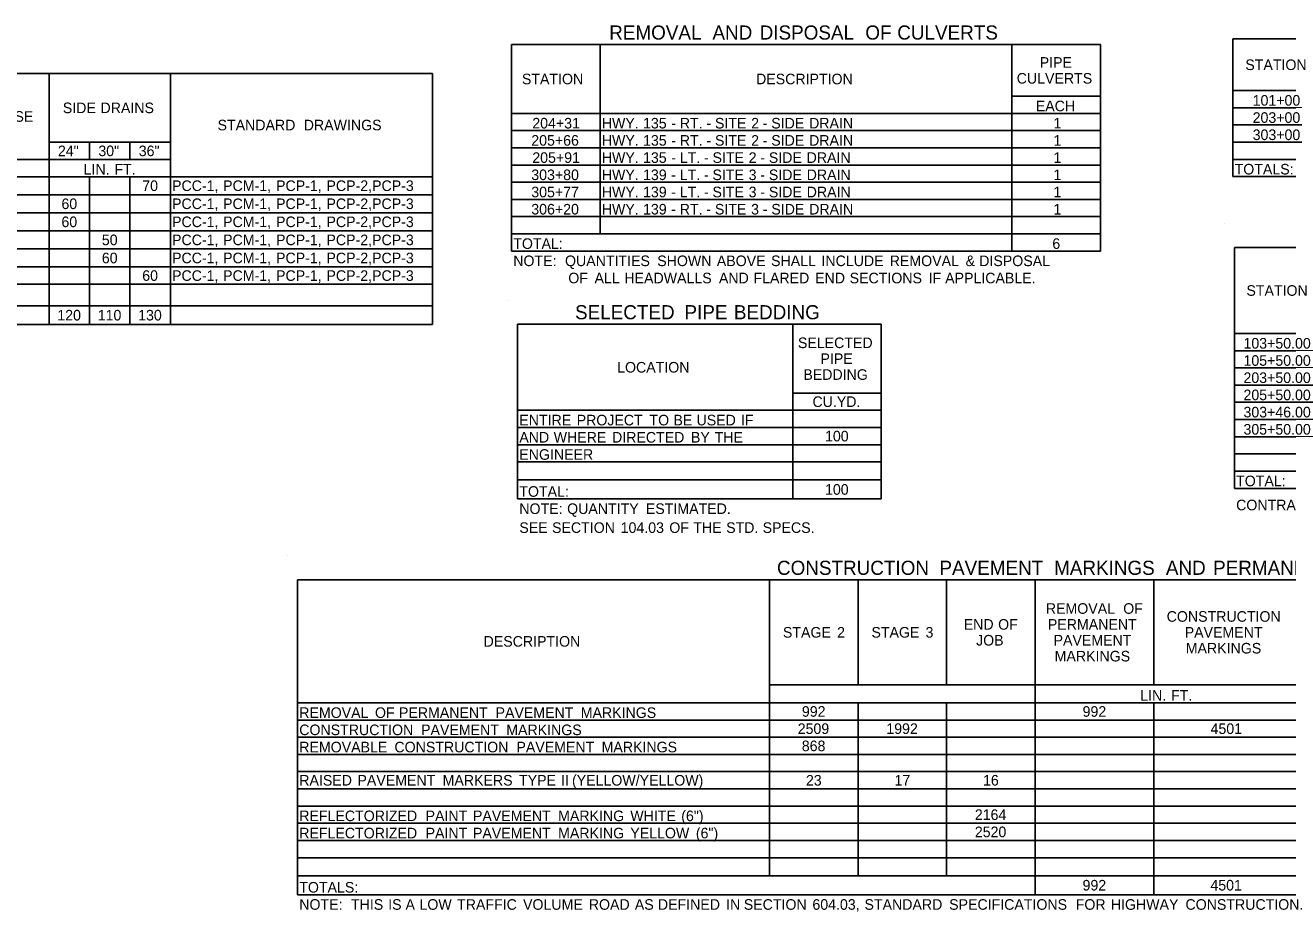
# Model space of a CAD drawing. Extents: x 1955554 to 1962042, y 565952 to 568347.
# Drawn here: x 1957367 to 1958082, y 566007 to 566510 of the extents above; entities that cross this region are included whole.
import ezdxf

# ---------------------------------------------------------------- set-up
doc = ezdxf.new("R2010")
doc.units = 0
doc.layers.add('Default', color=7, linetype='Continuous')
doc.layers.add('R_Border', color=7, linetype='Continuous')

msp = doc.modelspace()

# ---------------------------------------------------------------- linework, layer by layer
at = {"layer": 'Default'}
for p, q in [((1957642.33, 566498.81), (1957976.27, 566498.81)), ((1957642.33, 566381.81), (1957642.33, 566498.81)), ((1957692.55, 566391.56), (1957692.55, 566498.81)), ((1957926.06, 566381.81), (1957926.06, 566498.81)), ((1957976.27, 566381.81), (1957976.27, 566498.81)), ((1958051.36, 566502), (1958370.19, 566502)), ((1958051.36, 566424), (1958051.36, 566502)), ((1958051.36, 566424), (1958051.36, 566502)), ((1956897.02, 566482.45), (1957597.55, 566482.45)), ((1957380.13, 566340.1), (1957380.13, 566482.45)), ((1957448.87, 566340.1), (1957448.87, 566482.45)), ((1957597.55, 566340.1), (1957597.55, 566482.45)), ((1957597.55, 566340.1), (1957597.55, 566482.45)), ((1957926.06, 566469.56), (1957976.27, 566469.56)), ((1958051.36, 566472.75), (1958370.19, 566472.75)), ((1958051.36, 566463), (1958370.19, 566463)), ((1957642.33, 566459.81), (1957976.27, 566459.81)), ((1957692.55, 566391.56), (1957692.55, 566459.81)), ((1957926.06, 566381.81), (1957926.06, 566459.81)), ((1958051.36, 566453.25), (1958370.19, 566453.25)), ((1957642.33, 566450.06), (1957976.27, 566450.06)), ((1957380.13, 566443.45), (1957448.87, 566443.45)), ((1957403.04, 566433.7), (1957403.04, 566443.45)), ((1957403.04, 566433.7), (1957403.04, 566443.45)), ((1957425.95, 566433.7), (1957425.95, 566443.45)), ((1957425.95, 566433.7), (1957425.95, 566443.45)), ((1957448.87, 566433.7), (1957448.87, 566443.45)), ((1957642.33, 566440.31), (1957976.27, 566440.31)), ((1958051.36, 566443.5), (1958370.19, 566443.5)), ((1957153.44, 566433.7), (1957448.87, 566433.7)), ((1957380.13, 566433.7), (1957448.87, 566433.7)), ((1958051.36, 566433.75), (1958370.19, 566433.75)), ((1957642.33, 566430.56), (1957976.27, 566430.56)), ((1956897.02, 566423.95), (1957597.55, 566423.95)), ((1957403.04, 566350.82), (1957403.04, 566423.95)), ((1957403.04, 566340.1), (1957403.04, 566423.95)), ((1957425.95, 566350.82), (1957425.95, 566423.95)), ((1957425.95, 566340.1), (1957425.95, 566423.95)), ((1957448.87, 566423.95), (1957597.55, 566423.95)), ((1957448.87, 566350.82), (1957448.87, 566423.95)), ((1957642.33, 566420.81), (1957976.27, 566420.81)), ((1958051.36, 566424), (1958370.19, 566424)), ((1956897.02, 566413.71), (1957597.55, 566413.71)), ((1957448.87, 566413.71), (1957597.55, 566413.71)), ((1957642.33, 566411.06), (1957976.27, 566411.06)), ((1956897.02, 566403.47), (1957597.55, 566403.47)), ((1957448.87, 566403.47), (1957597.55, 566403.47)), ((1957642.33, 566401.31), (1957976.27, 566401.31)), ((1958046.37, 566397.47), (1958046.37, 566397.47)), ((1956897.02, 566393.24), (1957597.55, 566393.24)), ((1957448.87, 566393.24), (1957597.55, 566393.24)), ((1957642.33, 566391.56), (1957976.27, 566391.56)), ((1956897.02, 566383), (1957597.55, 566383)), ((1957448.87, 566383), (1957597.55, 566383)), ((1957642.33, 566381.81), (1957976.27, 566381.81)), ((1958052.22, 566383.82), (1958427.59, 566383.82)), ((1958052.22, 566247.32), (1958052.22, 566383.82)), ((1958052.22, 566247.32), (1958052.22, 566383.82)), ((1956897.02, 566372.76), (1957597.55, 566372.76)), ((1957448.87, 566372.76), (1957597.55, 566372.76)), ((1956897.02, 566363.01), (1957597.55, 566363.01)), ((1956897.02, 566350.82), (1957597.55, 566350.82)), ((1957253.87, 566350.82), (1957380.13, 566350.82)), ((1957380.13, 566350.82), (1957448.87, 566350.82)), ((1957448.87, 566350.82), (1957597.55, 566350.82)), ((1956897.02, 566340.1), (1957597.55, 566340.1)), ((1957645.77, 566340.3), (1957851.98, 566340.3)), ((1957645.77, 566241.34), (1957645.77, 566340.3)), ((1957645.77, 566241.34), (1957645.77, 566340.3)), ((1957801.77, 566241.34), (1957801.77, 566340.3)), ((1957851.98, 566241.34), (1957851.98, 566340.3)), ((1957851.98, 566241.34), (1957851.98, 566340.3)), ((1958052.22, 566335.07), (1958427.59, 566335.07)), ((1958052.22, 566325.32), (1958427.59, 566325.32)), ((1958052.22, 566315.57), (1958427.59, 566315.57)), ((1958052.22, 566305.82), (1958427.59, 566305.82)), ((1957801.77, 566301.3), (1957851.98, 566301.3)), ((1958052.22, 566296.07), (1958427.59, 566296.07)), ((1957645.77, 566291.55), (1957851.98, 566291.55)), ((1957801.77, 566241.34), (1957801.77, 566291.55)), ((1957645.77, 566281.8), (1957851.98, 566281.8)), ((1958052.22, 566286.32), (1958427.59, 566286.32)), ((1958052.22, 566276.57), (1958427.59, 566276.57)), ((1957645.77, 566272.05), (1957851.98, 566272.05)), ((1958052.22, 566266.82), (1958427.59, 566266.82)), ((1957645.77, 566262.3), (1957851.98, 566262.3)), ((1958052.22, 566257.07), (1958101.94, 566257.07)), ((1958052.22, 566257.07), (1958427.59, 566257.07)), ((1957645.77, 566252.06), (1957851.98, 566252.06)), ((1958052.22, 566247.32), (1958427.59, 566247.32)), ((1957645.77, 566241.34), (1957851.98, 566241.34)), ((1957515.14, 566209.11), (1957515.14, 566209.11)), ((1957520.99, 566195.46), (1958367.29, 566195.46)), ((1957520.99, 566017.03), (1957520.99, 566195.46)), ((1957520.99, 566017.03), (1957520.99, 566195.46)), ((1957788.63, 566027.76), (1957788.63, 566195.46)), ((1957838.84, 566135.98), (1957838.84, 566195.46)), ((1957889.05, 566135.98), (1957889.05, 566195.46)), ((1957939.27, 566017.03), (1957939.27, 566195.46)), ((1958006.54, 566135.98), (1958006.54, 566195.46)), ((1957788.63, 566135.98), (1958367.29, 566135.98)), ((1957520.99, 566125.75), (1958367.29, 566125.75)), ((1957788.63, 566027.76), (1957788.63, 566125.75)), ((1957838.84, 566027.76), (1957838.84, 566125.75)), ((1957838.84, 566027.76), (1957838.84, 566125.75)), ((1957889.05, 566027.76), (1957889.05, 566125.75)), ((1957889.05, 566027.76), (1957889.05, 566125.75)), ((1957939.27, 566017.03), (1957939.27, 566125.75)), ((1958006.54, 566017.03), (1958006.54, 566125.75)), ((1958006.54, 566017.03), (1958006.54, 566125.75)), ((1957520.99, 566116), (1958367.29, 566116)), ((1957520.99, 566106.25), (1958367.29, 566106.25)), ((1957520.99, 566096.5), (1958367.29, 566096.5)), ((1957520.99, 566086.75), (1958367.29, 566086.75)), ((1957520.99, 566077), (1958367.29, 566077)), ((1957520.99, 566067.25), (1958367.29, 566067.25)), ((1957520.99, 566057.5), (1958367.29, 566057.5)), ((1957520.99, 566047.75), (1958367.29, 566047.75)), ((1957520.99, 566038), (1958367.29, 566038)), ((1957520.99, 566027.76), (1958367.29, 566027.76)), ((1957520.99, 566017.03), (1958367.29, 566017.03))]:
    msp.add_line(p, q, dxfattribs=at)
at = {"layer": 'R_Border'}
msp.add_line((1957639.92, 566353.95), (1957639.92, 566353.95), dxfattribs=at)

# ---------------------------------------------------------------- texts
at = {"layer": 'Default'}
for s, height, p in [('REMOVAL', 8, (1957697.72, 566501.64)), (' AND', 8, (1957753.28, 566501.64)), (' DISPOSAL', 8, (1957780.05, 566501.64)), (' OF', 8, (1957839.97, 566501.64)), (' CULVERTS', 8, (1957858.08, 566501.64)), ('PIPE', 6, (1957941.82, 566485.69)), ('STATION', 6, (1958058.41, 566484.38)), ('STATION', 6, (1957648.21, 566476.31)), ('DESCRIPTION', 6, (1957780.99, 566476.31)), ('CULVERTS', 6, (1957928.78, 566476.69)), ('EACH', 6, (1957939.61, 566461.01)), ('101+00', 6, (1958062.57, 566464.2)), (' COURSE', 6, (1957334.65, 566455.07)), ('SIDE', 6, (1957387.89, 566459.95)), (' DRAINS', 6, (1957407.04, 566459.95)), ('203+00', 6, (1958062.57, 566454.45)), ('STANDARD', 6, (1957475.65, 566450.2)), (' DRAWINGS', 6, (1957522.28, 566450.2)), ('204+31', 6, (1957654.11, 566451.26)), ('HWY.', 6, (1957693.52, 566451.26)), (' 135', 6, (1957714.68, 566451.26)), (' -', 6, (1957730.65, 566451.26)), (' RT.', 6, (1957735.51, 566451.26)), (' -', 6, (1957750.61, 566451.26)), (' SITE', 6, (1957755.46, 566451.26)), (' 2', 6, (1957775.98, 566451.26)), (' -', 6, (1957782.52, 566451.26)), (' SIDE', 6, (1957787.38, 566451.26)), (' DRAIN', 6, (1957808.83, 566451.26)), ('1', 6, (1957949.6, 566451.26)), ('205+66', 6, (1957653.53, 566441.51)), ('HWY.', 6, (1957693.52, 566441.51)), (' 135', 6, (1957714.68, 566441.51)), (' RT.', 6, (1957735.51, 566441.51)), (' SITE', 6, (1957755.46, 566441.51)), (' 2', 6, (1957775.98, 566441.51)), (' SIDE', 6, (1957787.38, 566441.51)), (' DRAIN', 6, (1957808.83, 566441.51)), ('1', 6, (1957949.6, 566441.51)), ('303+00', 6, (1958062.57, 566444.7)), ('24"', 6, (1957385.14, 566435.57)), ('30"', 6, (1957408.06, 566435.57)), ('36"', 6, (1957430.97, 566435.57)), (' -', 6, (1957730.65, 566441.51)), (' -', 6, (1957750.61, 566441.51)), (' -', 6, (1957782.52, 566441.51)), ('205+91', 6, (1957654.11, 566431.76)), ('HWY.', 6, (1957693.52, 566431.76)), (' 135', 6, (1957714.68, 566431.76)), (' -', 6, (1957730.65, 566431.76)), (' LT.', 6, (1957735.51, 566431.76)), (' -', 6, (1957749.21, 566431.76)), (' SITE', 6, (1957754.07, 566431.76)), (' 2', 6, (1957774.58, 566431.76)), (' -', 6, (1957781.13, 566431.76)), (' SIDE', 6, (1957785.99, 566431.76)), (' DRAIN', 6, (1957807.43, 566431.76)), ('1', 6, (1957949.6, 566431.76)), ('TOTALS:', 6, (1958052.34, 566425.2)), ('LIN.', 6, (1957399.71, 566425.15)), (' FT.', 6, (1957414.96, 566425.15)), ('303+80', 6, (1957653.54, 566422.01)), ('HWY.', 6, (1957693.52, 566422.01)), (' 139', 6, (1957714.68, 566422.01)), (' -', 6, (1957730.61, 566422.01)), (' LT.', 6, (1957735.47, 566422.01)), (' -', 6, (1957749.18, 566422.01)), (' SITE', 6, (1957754.03, 566422.01)), (' 3', 6, (1957774.55, 566422.01)), (' -', 6, (1957781.16, 566422.01)), (' SIDE', 6, (1957786.01, 566422.01)), (' DRAIN', 6, (1957807.46, 566422.01)), ('1', 6, (1957949.6, 566422.01)), ('70', 6, (1957432.95, 566415.83)), ('PCC-1,', 6, (1957449.84, 566415.83)), (' PCM-1,', 6, (1957476.57, 566415.83)), (' PCP-1,', 6, (1957506.57, 566415.83)), (' PCP-2,PCP-3', 6, (1957535.17, 566415.83)), ('305+77', 6, (1957653.53, 566412.26)), ('HWY.', 6, (1957693.52, 566412.26)), (' 139', 6, (1957714.68, 566412.26)), (' LT.', 6, (1957735.47, 566412.26)), (' SITE', 6, (1957754.03, 566412.26)), (' 3', 6, (1957774.55, 566412.26)), (' SIDE', 6, (1957786.01, 566412.26)), (' DRAIN', 6, (1957807.46, 566412.26)), ('1', 6, (1957949.6, 566412.26)), ('60', 6, (1957387.12, 566405.59)), ('PCC-1,', 6, (1957449.84, 566405.59)), (' PCM-1,', 6, (1957476.57, 566405.59)), (' PCP-1,', 6, (1957506.57, 566405.59)), (' PCP-2,PCP-3', 6, (1957535.17, 566405.59)), (' -', 6, (1957730.61, 566412.26)), (' -', 6, (1957749.18, 566412.26)), (' -', 6, (1957781.16, 566412.26)), ('306+20', 6, (1957653.54, 566402.51)), ('HWY.', 6, (1957693.52, 566402.51)), (' 139', 6, (1957714.68, 566402.51)), (' -', 6, (1957730.61, 566402.51)), (' RT.', 6, (1957735.47, 566402.51)), (' -', 6, (1957750.57, 566402.51)), (' SITE', 6, (1957755.43, 566402.51)), (' 3', 6, (1957775.94, 566402.51)), (' -', 6, (1957782.55, 566402.51)), (' SIDE', 6, (1957787.41, 566402.51)), (' DRAIN', 6, (1957808.86, 566402.51)), ('1', 6, (1957949.6, 566402.51)), ('60', 6, (1957387.12, 566395.36)), ('PCC-1,', 6, (1957449.84, 566395.36)), (' PCM-1,', 6, (1957476.57, 566395.36)), (' PCP-1,', 6, (1957506.57, 566395.36)), (' PCP-2,PCP-3', 6, (1957535.17, 566395.36)), ('50', 6, (1957410.04, 566385.12)), ('PCC-1,', 6, (1957449.84, 566385.12)), (' PCM-1,', 6, (1957476.57, 566385.12)), (' PCP-1,', 6, (1957506.57, 566385.12)), (' PCP-2,PCP-3', 6, (1957535.17, 566385.12)), ('TOTAL:', 6, (1957643.31, 566383.01)), ('6', 6, (1957948.98, 566383.01)), ('60', 6, (1957410.04, 566374.88)), ('PCC-1,', 6, (1957449.84, 566374.88)), (' PCM-1,', 6, (1957476.57, 566374.88)), (' PCP-1,', 6, (1957506.57, 566374.88)), (' PCP-2,PCP-3', 6, (1957535.17, 566374.88)), ('NOTE:', 6, (1957643.31, 566373.26)), ('  QUANTITIES', 6, (1957668.2, 566373.26)), (' SHOWN', 6, (1957722.72, 566373.26)), (' ABOVE', 6, (1957756.5, 566373.26)), (' SHALL', 6, (1957787.27, 566373.26)), (' INCLUDE', 6, (1957815.86, 566373.26)), (' REMOVAL', 6, (1957854.54, 566373.26)), (' &', 6, (1957897.57, 566373.26)), (' DISPOSAL', 6, (1957905.3, 566373.26)), ('60', 6, (1957432.95, 566364.89)), ('PCC-1,', 6, (1957449.84, 566364.89)), (' PCM-1,', 6, (1957476.57, 566364.89)), (' PCP-1,', 6, (1957506.57, 566364.89)), (' PCP-2,PCP-3', 6, (1957535.17, 566364.89)), ('              OF', 6, (1957643.31, 566363.51)), (' ALL', 6, (1957687.16, 566363.51)), (' HEADWALLS', 6, (1957704.1, 566363.51)), (' AND', 6, (1957757.7, 566363.51)), (' FLARED', 6, (1957777.28, 566363.51)), (' END', 6, (1957812.24, 566363.51)), (' SECTIONS', 6, (1957831.82, 566363.51)), (' IF', 6, (1957876.57, 566363.51)), (' APPLICABLE.', 6, (1957885.97, 566363.51)), ('STATION', 6, (1958059.02, 566356.44)), ('120', 6, (1957384.8, 566342.46)), ('110', 6, (1957407.71, 566342.46)), ('130', 6, (1957430.62, 566342.46)), ('SELECTED', 8, (1957678.34, 566343.13)), (' PIPE', 8, (1957737.42, 566343.13)), (' BEDDING', 8, (1957765.44, 566343.13)), ('SELECTED', 6, (1957804.72, 566326.8)), ('103+50.00', 6, (1958057.36, 566326.52)), ('LOCATION', 6, (1957702.22, 566312.93)), ('PIPE', 6, (1957817.53, 566317.8)), ('105+50.00', 6, (1958057.36, 566316.77)), ('BEDDING', 6, (1957807.8, 566308.8)), ('203+50.00', 6, (1958057.36, 566307.02)), ('205+50.00', 6, (1958057.36, 566297.27)), ('CU.YD.', 6, (1957812.96, 566293.43)), ('ENTIRE', 6, (1957646.75, 566283)), (' PROJECT', 6, (1957677.04, 566283)), (' TO', 6, (1957718.33, 566283)), (' BE', 6, (1957731.93, 566283)), (' USED', 6, (1957745, 566283)), (' IF', 6, (1957770.17, 566283)), ('303+46.00', 6, (1958057.36, 566287.52)), ('305+50.00', 6, (1958057.36, 566277.77)), ('AND', 6, (1957646.75, 566273.25)), (' WHERE', 6, (1957664, 566273.25)), (' DIRECTED', 6, (1957697.09, 566273.25)), (' BY', 6, (1957741.82, 566273.25)), (' THE', 6, (1957755.27, 566273.25)), ('100', 6, (1957820.09, 566273.93)), ('ENGINEER', 6, (1957646.75, 566263.5)), ('TOTAL:', 6, (1958053.19, 566248.52)), ('TOTAL:', 6, (1957646.75, 566242.54)), ('100', 6, (1957820.09, 566243.7)), ('NOTE:', 6, (1957646.75, 566232.79)), (' QUANTITY', 6, (1957671.63, 566232.79)), (' ESTIMATED.', 6, (1957716.29, 566232.79)), ('CONTRACTOR', 6, (1958053.19, 566234.87)), ('SEE', 6, (1957646.75, 566222.06)), (' SECTION', 6, (1957663.08, 566222.06)), (' 104.03', 6, (1957701.99, 566222.06)), (' OF', 6, (1957729.56, 566222.06)), (' THE', 6, (1957743.15, 566222.06)), (' STD.', 6, (1957761.8, 566222.06)), (' SPECS.', 6, (1957782.49, 566222.06)), ('CONSTRUCTION', 8, (1957792.85, 566198.28)), (' PAVEMENT', 8, (1957882, 566198.28)), (' MARKINGS', 8, (1957946.99, 566198.28)), (' AND', 8, (1958010.4, 566198.28)), (' PERMANENT', 8, (1958037.17, 566198.28)), ('REMOVAL', 6, (1957945.28, 566176.22)), (' OF', 6, (1957986.95, 566176.22)), ('CONSTRUCTION', 6, (1958013.82, 566171.72)), ('STAGE', 6, (1957796.22, 566162.72)), (' 2', 6, (1957824.69, 566162.72)), ('STAGE', 6, (1957846.4, 566162.72)), (' 3', 6, (1957874.87, 566162.72)), ('END', 6, (1957898.73, 566167.22)), (' OF', 6, (1957916.01, 566167.22)), ('PERMANENT', 6, (1957946.44, 566167.22)), ('PAVEMENT', 6, (1958024.04, 566162.72)), ('DESCRIPTION', 6, (1957626.5, 566157.6)), ('JOB', 6, (1957905.75, 566158.22)), ('PAVEMENT', 6, (1957949.7, 566158.22)), ('MARKINGS', 6, (1958024.63, 566153.72)), ('MARKINGS', 6, (1957950.29, 566149.22)), ('LIN.', 6, (1957998.82, 566126.95)), (' FT.', 6, (1958014.08, 566126.95)), ('992', 6, (1957806.97, 566117.87)), ('992', 6, (1957966.14, 566117.87)), ('REMOVAL', 6, (1957521.97, 566117.2)), (' OF', 6, (1957562.67, 566117.2)), (' PERMANENT', 6, (1957576.26, 566117.2)), (' PAVEMENT', 6, (1957631.06, 566117.2)), (' MARKINGS', 6, (1957679.34, 566117.2)), ('CONSTRUCTION', 6, (1957521.97, 566107.45)), (' PAVEMENT', 6, (1957588.82, 566107.45)), (' MARKINGS', 6, (1957637.1, 566107.45)), ('2509', 6, (1957804.6, 566108.12)), ('1992', 6, (1957854.85, 566108.12)), ('4501', 6, (1958038.7, 566108.12)), ('REMOVABLE', 6, (1957521.97, 566097.7)), (' CONSTRUCTION', 6, (1957573.7, 566097.7)), (' PAVEMENT', 6, (1957642.88, 566097.7)), (' MARKINGS', 6, (1957691.17, 566097.7)), ('868', 6, (1957806.93, 566098.37)), ('RAISED', 6, (1957521.97, 566078.87)), (' PAVEMENT', 6, (1957552.74, 566078.87)), (' MARKERS', 6, (1957601.02, 566078.87)), (' TYPE', 6, (1957644.37, 566078.87)), (' II', 6, (1957668.15, 566078.87)), (' (YELLOW/YELLOW)', 6, (1957674.39, 566078.87)), ('23', 6, (1957809.27, 566078.87)), ('17', 6, (1957859.48, 566078.87)), ('16', 6, (1957909.69, 566078.87)), ('REFLECTORIZED', 6, (1957521.97, 566058.7)), (' PAINT', 6, (1957591.39, 566058.7)), (' PAVEMENT', 6, (1957618.24, 566058.7)), (' MARKING', 6, (1957666.52, 566058.7)), (' WHITE', 6, (1957707.45, 566058.7)), (' (6")', 6, (1957736.34, 566058.7)), ('2164', 6, (1957905.04, 566059.37)), ('REFLECTORIZED', 6, (1957521.97, 566048.95)), (' PAINT', 6, (1957591.39, 566048.95)), (' PAVEMENT', 6, (1957618.24, 566048.95)), (' MARKING', 6, (1957666.52, 566048.95)), (' YELLOW', 6, (1957707.45, 566048.95)), (' (6")', 6, (1957744.63, 566048.95)), ('2520', 6, (1957905.04, 566049.62)), ('TOTALS:', 6, (1957521.97, 566018.23)), ('992', 6, (1957966.12, 566019.4)), ('4501', 6, (1958038.61, 566019.4)), ('NOTE:', 6, (1957521.97, 566008.48)), ('  THIS', 6, (1957546.85, 566008.48)), (' IS', 6, (1957570.17, 566008.48)), (' A', 6, (1957579.98, 566008.48)), (' LOW', 6, (1957587.91, 566008.48)), (' TRAFFIC', 6, (1957609.24, 566008.48)), (' VOLUME', 6, (1957646.63, 566008.48)), (' ROAD', 6, (1957683.91, 566008.48)), (' AS', 6, (1957710.02, 566008.48)), (' DEFINED', 6, (1957723.09, 566008.48)), (' IN', 6, (1957761.77, 566008.48)), (' SECTION', 6, (1957771.79, 566008.48)), (' 604.03,', 6, (1957810.7, 566008.48)), (' STANDARD', 6, (1957840.24, 566008.48)), (' SPECIFICATIONS', 6, (1957888.24, 566008.48)), (' FOR', 6, (1957960.01, 566008.48)), (' HIGHWAY', 6, (1957979.92, 566008.48)), (' CONSTRUCTION.', 6, (1958022.24, 566008.48))]:
    msp.add_text(s, height=height, dxfattribs=at).set_placement(p)

doc.saveas('drawing.dxf')
